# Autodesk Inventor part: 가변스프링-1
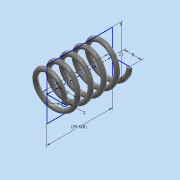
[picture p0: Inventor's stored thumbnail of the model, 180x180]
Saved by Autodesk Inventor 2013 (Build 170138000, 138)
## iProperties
Created: 2018-10
Part Number: 가변스프링-1
Material: 스테인레스 스틸
Document SubType Name: Modeling
Designer: Administrator
Density: 8.08 g/cm^3
Mass: 6.28226 g
Surface Area: 15.7852 cm^2
Volume: 0.777508 cm^3
Author: Administrator
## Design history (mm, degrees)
sketch "스케치1"
  geometry: L1 (0, 0)-(0, 29.428); L2 (0, 0)-(8, 0); L3 (0, 29.428)-(8, 29.428); C1 r 1 at (8, 0)
  constraints: 6 end point, 1 centre point, 1 coincident, 1 parallel, 1 perpendicular, 1 vertical
  dimensions: "d0" = 29.42836 distance of L1.start L1.end (derived); "d1" = 8 distance of L1.start L2.end; "d2" = 8 distance of L1.end L3.end; "d3" = 2 diameter of C1
feature "코일1" sketch "스케치1" pitch "d4" = 10; turns "d6" = 5; dims "d5" = 29.42836 (= d0), "d7" = 0, angle "d8" = 90 deg, angle "d9" = 90 deg, "d10" = 0, "d11" = 0
sketch "스케치2"
  geometry: L1 (29.428, 11.5)-(0, 11.5); L2 (0, 11.5)-(0, -11.5); L3 (0, -11.5)-(29.428, -11.5); L4 (29.428, -11.5)-(29.428, 11.5); 2 further points
  constraints: 8 end point, 2 parallel, 1 coincident, 1 horizontal, 1 midpoint, 1 perpendicular
  dimensions: "d12" = 29.42836 distance between parallel lines of L2 L4 (derived); "d14" = 23 distance between parallel lines of L1 L3
extrude "돌출1" sketch "스케치2" stored distance "d15" = 0; taper "d16" = 0 deg
node "솔리드1"
